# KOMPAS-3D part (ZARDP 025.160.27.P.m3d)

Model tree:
1. Плоскость XY
2. Плоскость ZX
3. Плоскость ZY
4. Ось X
5. Ось Y
6. Ось Z
7. Начало координат
8. Булева операция:1
9. Булева операция:2
10. Булева операция:3
11. Булева операция:4
